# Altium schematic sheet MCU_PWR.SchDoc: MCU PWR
size A4; Date: Not used; ApprovedBy: Not used; CheckedBy: Not used; Author: Not used; CompanyName: STMicroelectronics; DrawnBy: Not used; Engineer: Not used; Organization: Not used; Address1: Not used; Address2: Not used; Address3: Not used; Address4: Not used; DocumentNumber: 5; Revision: Not used; SheetNumber: 5; SheetTotal: 16
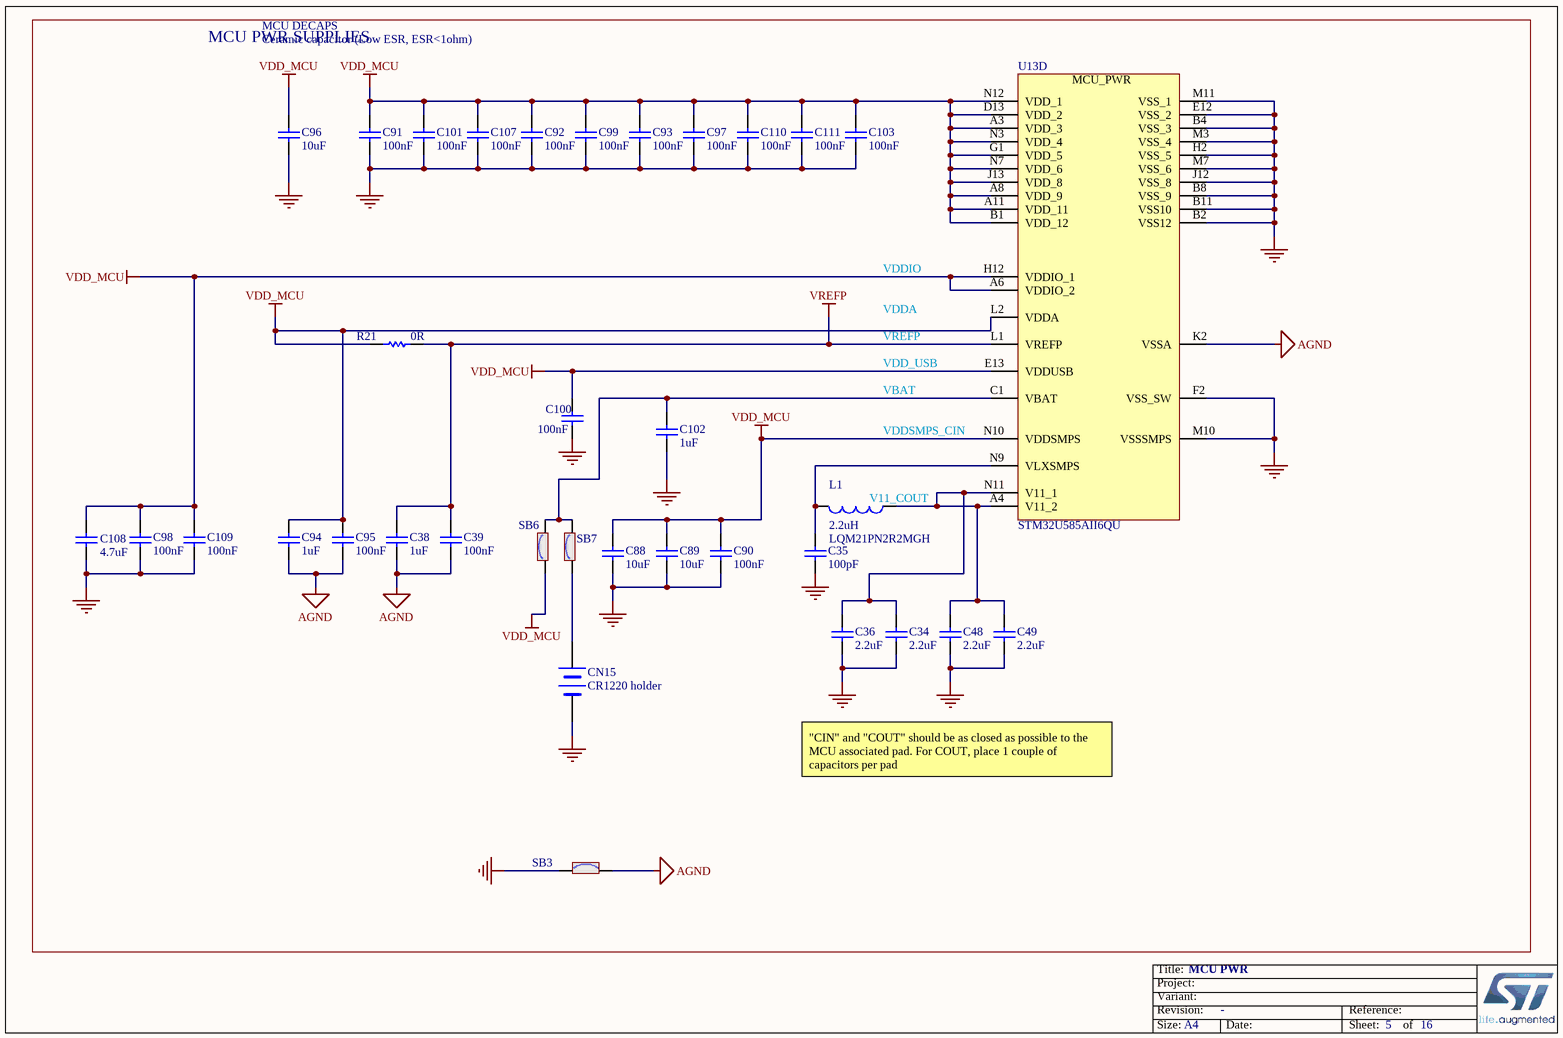
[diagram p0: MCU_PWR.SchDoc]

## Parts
C34  value 2.2uF  [C0402]
C35  value 100pF  [C0402]
C36  value 2.2uF  [C0402]
C38  value 1uF  [C0603]
C39  value 100nF  [C0402]
C48  value 2.2uF  [C0402]
C49  value 2.2uF  [C0402]
C88  value 10uF  [C0402]  (hidden comment: Capacitor)
C89  value 10uF  [C0402]  (hidden comment: Capacitor)
C90  value 100nF  [C0402]
C91  value 100nF  [C0402]
C92  value 100nF  [C0402]
C93  value 100nF  [C0402]
C94  value 1uF  [C0603]
C95  value 100nF  [C0402]
C96  value 10uF  [C0402]  (hidden comment: Capacitor)
C97  value 100nF  [C0402]
C98  value 100nF  [C0402]
C99  value 100nF  [C0402]
C100  value 100nF  [C0402]
C101  value 100nF  [C0402]
C102  value 1uF  [C0603]
C103  value 100nF  [C0402]
C107  value 100nF  [C0402]
C108  value 4.7uF  [C0603]
C109  value 100nF  [C0402]
C110  value 100nF  [C0402]
C111  value 100nF  [C0402]
CN15  value CR1220 holder  [BAT_HARWIN_S8411-45R_SMD_2P]
L1  value 2.2uH  Manufacturer_Part_Number: LQM21PN2R2MGH  [L0805_H0P9]  (hidden comment: Inductor)
R21  value 0R  [R0402]
SB3  (no value)  [SOLDER-BRIDGE_R0603-0R]
SB6  (no value)  [SOLDER-BRIDGE_R0603-0R]
SB7  (no value)  [SOLDER-BRIDGE_R0603-0R]
U13  STM32U585AII6QU  [ICC_UFBGA169_7X7_P050]  (part D of 4)

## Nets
AGND: C38.2 C39.1 C94.2 C95.1 SB3.2 U13.K2(VSSA)
GND: C34.1 C35.1 C36.1 C48.1 C49.1 C88.1 C89.1 C90.1 C91.1 C92.1 C93.1 C96.1 C97.1 C98.1 C99.1 C100.1 C101.1 C102.2 C103.1 C107.1 C108.1 C109.1 C110.1 C111.1 CN15.2(-) SB3.1 U13.B2(VSS12) U13.B4(VSS_3) U13.B8(VSS_9) U13.B11(VSS10) U13.E12(VSS_2) U13.F2(VSS_SW) U13.H2(VSS_5) U13.J12(VSS_8) U13.M3(VSS_4) U13.M7(VSS_6) U13.M10(VSSSMPS) U13.M11(VSS_1)
VDD_MCU: C88.2 C89.2 C90.2 C91.2 C92.2 C93.2 C94.1 C95.2 C96.2 C97.2 C98.2 C99.2 C100.2 C101.2 C103.2 C107.2 C108.2 C109.2 C110.2 C111.2 R21.1 SB6.1 U13.A3(VDD_3) U13.A6(VDDIO_2) U13.A8(VDD_9) U13.A11(VDD_11) U13.B1(VDD_12) U13.D13(VDD_2) U13.E13(VDDUSB) U13.G1(VDD_5) U13.H12(VDDIO_1) U13.J13(VDD_8) U13.L2(VDDA) U13.N3(VDD_4) U13.N7(VDD_6) U13.N10(VDDSMPS) U13.N12(VDD_1)
VREFP: C38.1 C39.2 R21.2 U13.L1(VREFP)
NetC34_2: C34.2 C36.2 C48.2 C49.2 L1.1 U13.A4(V11_2) U13.N11(V11_1)
NetC35_2: C35.2 L1.2 U13.N9(VLXSMPS)
NetC102_1: C102.1 SB6.2 SB7.2 U13.C1(VBAT)
NetCN15_1: CN15.1(+) SB7.1

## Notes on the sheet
- MCU PWR SUPPLIES
- MCU DECAPS
- Ceramic capacitor (Low ESR, ESR<1ohm)
- VDDA
- VDDIO
- VDD_USB
- VREFP
- VDDSMPS_CIN
- VBAT
- (near L1) V11_COUT
- "CIN" and "COUT" should be as closed as possible to the MCU associated pad. For COUT, place 1 couple of capacitors per pad

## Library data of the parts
C34 C36 C48 C49 = MCD-01823: Capacitor,MLCC,2.2uF,6V3,X5R,10%,0402,T=0.5; Manufacturer_Part_Number: GRM155R60J225KE95D; Manufacturer: MURATA; ECCN_US: EAR99; ECCN_EU: NEC; Provided_By: SUBCO
C35 = MCD-00205: Capacitor, MLCC, 100pF, 50V, NPO, 5%, 0402, T=0,5mm; Manufacturer_Part_Number: CC0402JRNPO9BN101; Manufacturer: YAGEO; Provided_By: Subcon; Initial_Board_Reference: MB1361
C38 C94 C102 = MCD-00010: Capacitor, MLCC, 1uF, 16V, X5R, 10%, 0603, T=0,8mm; Manufacturer_Part_Number: CC0603KRX5R7BB105; Manufacturer: YAGEO; Provided_By: Subcon; Initial_Board_Reference: MB1274
C39 C90-C93 C95 C97-C101 C103 C107 C109-C111 = MCD-00006: Capacitor, MLCC, 100nF, 16V, X7R, 10%, 0402, T=0.5mm; Manufacturer_Part_Number: CC0402KRX7R7BB104; Manufacturer: YAGEO; Alternate_Manufacturer_Part_Number: GCM155R71C104KA55D; Alternate_Manufacturer: MURATA; Provided_By: SUBCO; ECCN_US: EAR99; ECCN_EU: NEC
C88 C89 C96 = MCD-01355: Capacitor, MLCC, 10uF, 4V, X5R, 20%, 0402, T=0,5mm; Manufacturer_Part_Number: GRM155R60G106ME44; Manufacturer: MURATA; ECCN_US: EAR99; ECCN_EU: NEC; Provided_By: Subcon; Initial_Board_Reference: MB1372
C108 = MCD-00009: Capacitor, MLCC, 4.7uF, 16V, X5R, 10%, 0603, T=0.8mm; Manufacturer_Part_Number: CC0603KRX5R7BB475; Manufacturer: YAGEO; ECCN_US: EAR99; ECCN_EU: NEC; Provided_By: SUBCO
CN15 = MCD-00558: Battery Coin Cell holder, CR1220_12mm, Height 4.25mm; Part_Type: Connector; Manufacturer_Part_Number: S8411-45R; Manufacturer: HARWIN; Provided_By: Subcon; Initial_Board_Reference: MB1331
L1 = MCD-01060: Inductor, 2.2uH, 20%, Isat 0.7A, DCR 0.156Ohm, 0805; Manufacturer: MURATA; Part_Preference: Recommended
R21 = MCD-00052: Resistor,0R,0402,5%,1/16W; Manufacturer_Part_Number: RC0402JR-070RL; Manufacturer: YAGEO; Provided_By: Subcon; Initial_Board_Reference: mb1274
SB3 = MCD-00071: Solder Bridge ON; Part_Type: Mechanical; Provided_By: Subcon; Initial_Board_Reference: MB1274
SB6 SB7 = MCD-00071: Solder Bridge ON; Part_Type: Mechanical; Provided_By: Subcon; Initial_Board_Reference: mb1274
U13 = MCD-02055: STM32U585AII6Q MCU,Low Power BGA169 7x7, pitch0.5, with encryption, Q for Int SMPS.; Part_Type: IC; Manufacturer: STMICROELECTRONICS; ECCN_US: 5A002A4; Provided_By: SUBCO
